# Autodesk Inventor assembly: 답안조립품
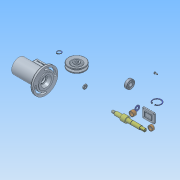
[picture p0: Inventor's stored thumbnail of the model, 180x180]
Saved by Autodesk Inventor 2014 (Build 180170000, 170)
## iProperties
Created: 2017-05
Part Number: 답안조립품
Document SubType Name: Assembly
Designer: NET
Author: NET
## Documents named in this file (13)
- C:\Users\NET\Desktop\470507V1006\답안조립품.iam
- C:\Users\NET\Desktop\470507V1006\본체.ipt
- C:\Users\NET\Desktop\470507V1006\V-벨트풀리.ipt
- C:\Users\NET\Desktop\470507V1006\너트 M10.ipt
- C:\Users\NET\Desktop\470507V1006\멈춤링 15 x 1.ipt
- C:\Users\NET\Desktop\470507V1006\멈춤링 35x1.6.ipt
- C:\Users\NET\Desktop\470507V1006\베어링 15 x 35 x 11.ipt
- C:\Users\NET\Desktop\470507V1006\볼트 M4 x 10.ipt
- C:\Users\NET\Desktop\470507V1006\축.ipt
- C:\Users\NET\Desktop\470507V1006\탑 커버.ipt
- C:\Users\NET\Desktop\470507V1006\부시2.ipt
- C:\Users\NET\Desktop\470507V1006\부시1.ipt
- C:\Users\NET\Desktop\470507V1006\와셔 10x21.ipt
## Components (2 placed, 2 different names)
1. V-벨트풀리:1
2. ISO 4017 M4 x 10:1
